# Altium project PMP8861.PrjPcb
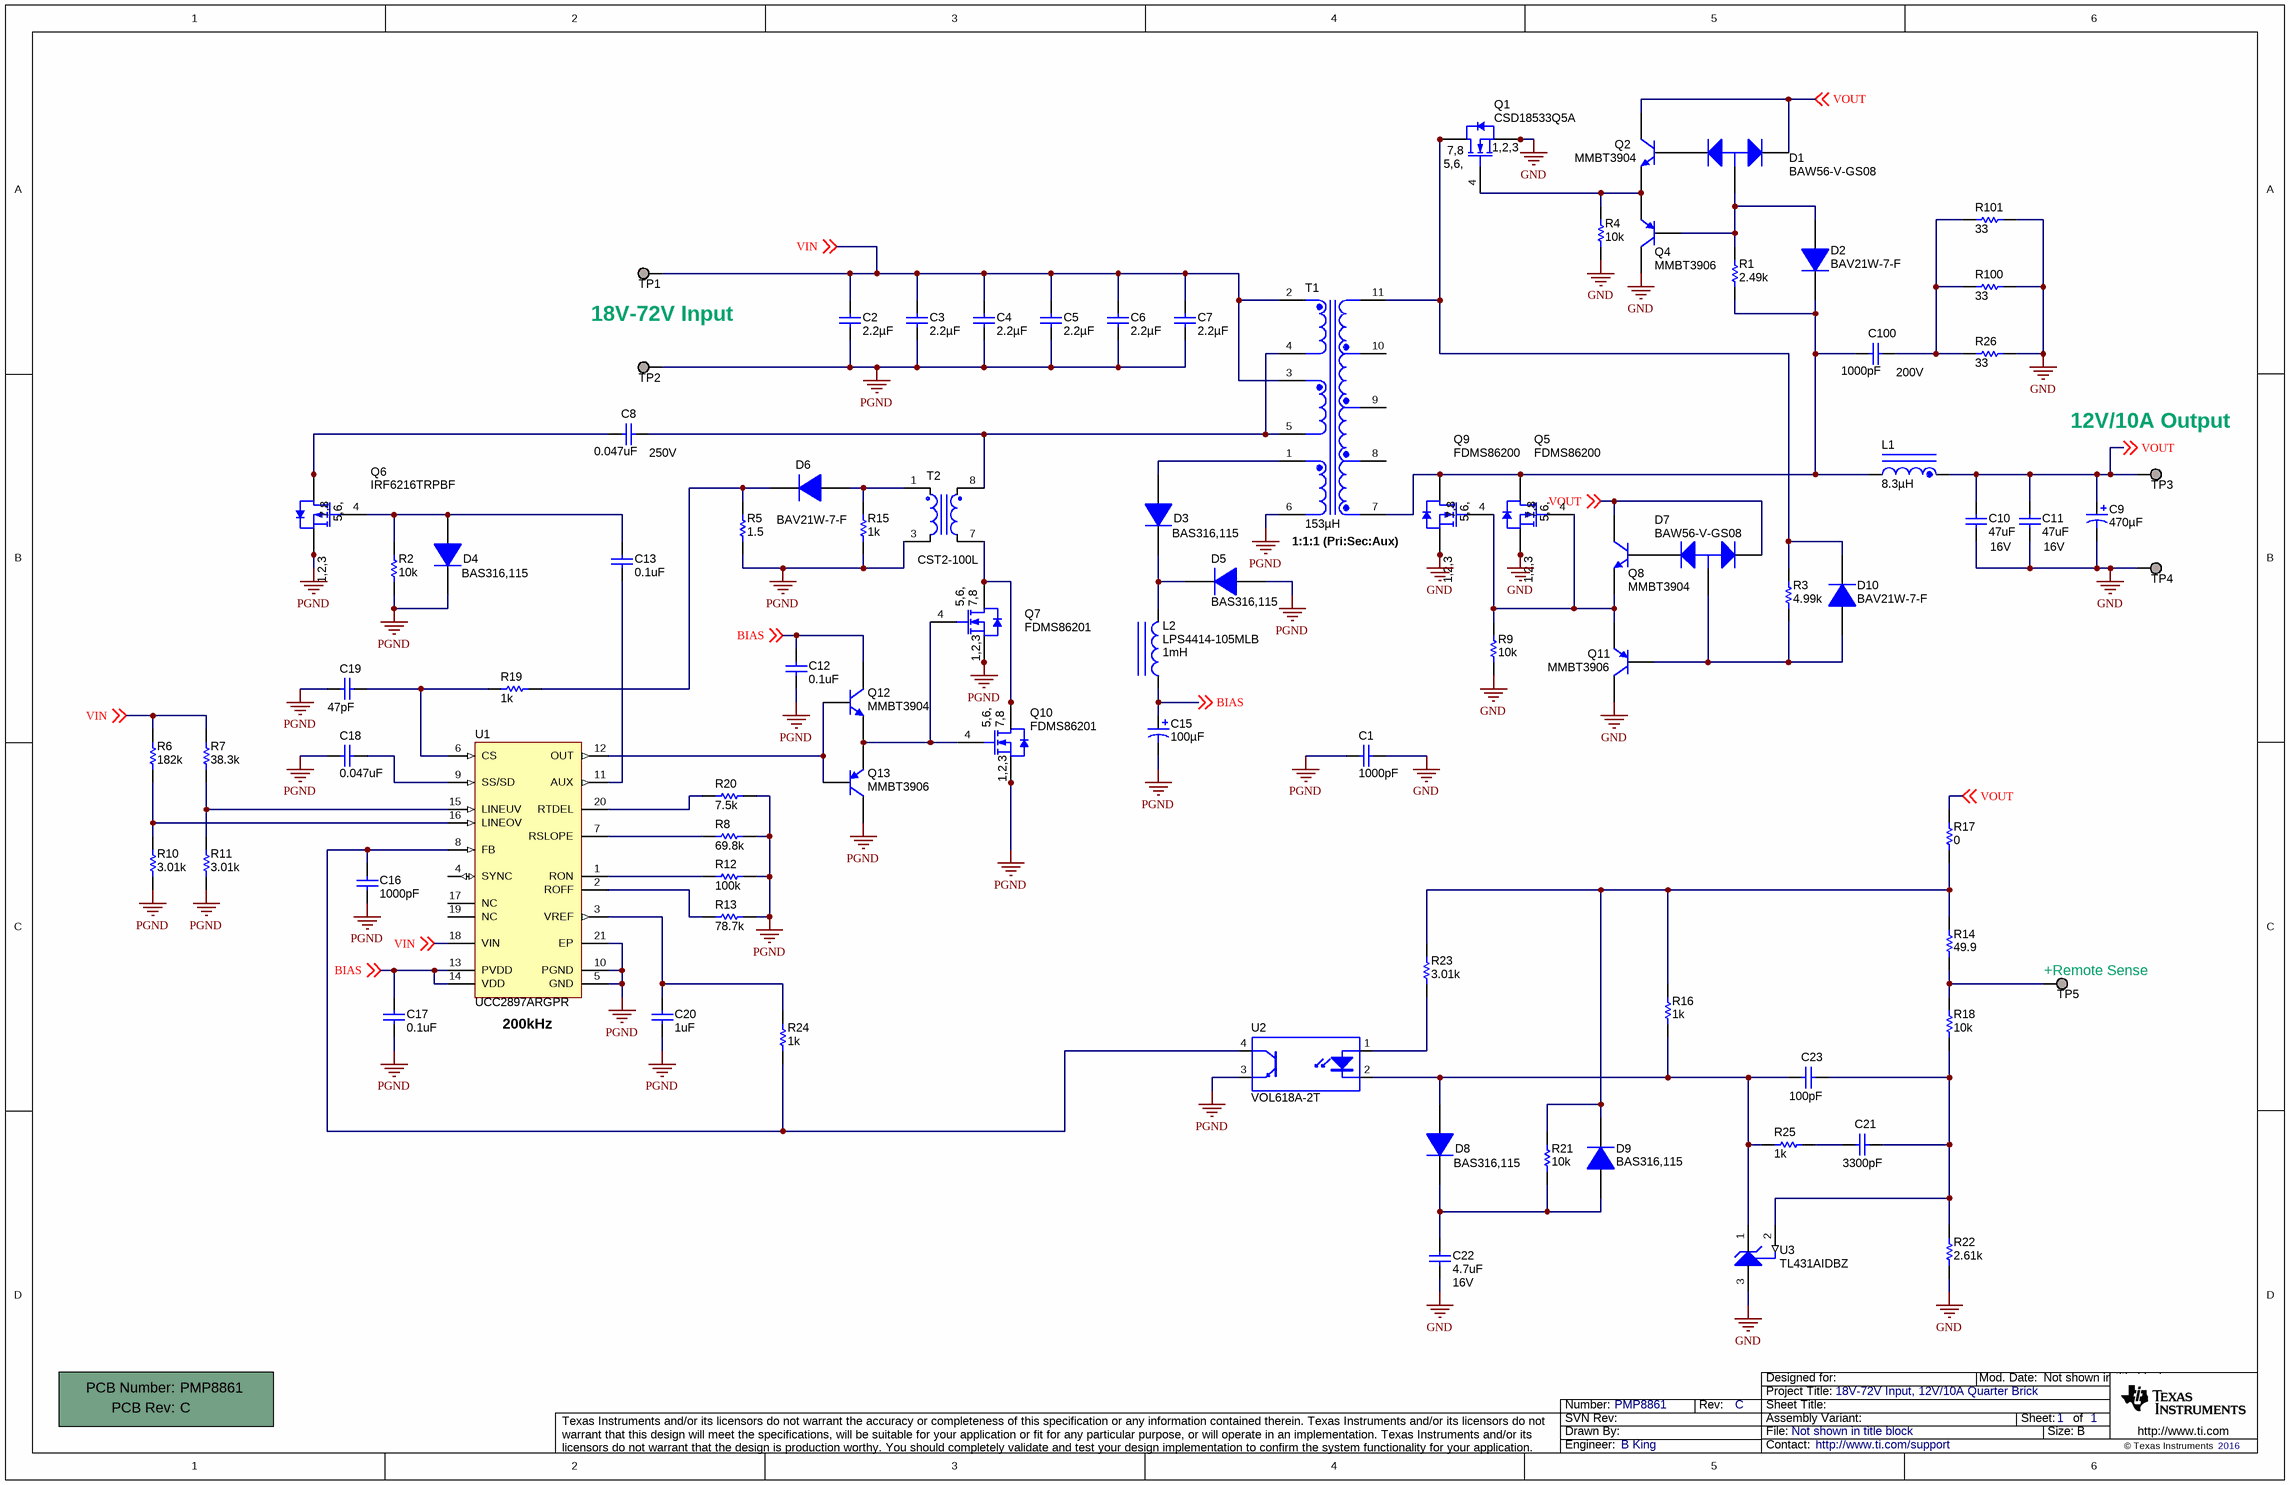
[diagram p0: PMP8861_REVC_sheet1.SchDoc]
TechSupport: http://www.ti.com/support; SCH_Rev: C; PRJ_Title: 18V-72V Input, 12V/10A Quarter Brick; PRJ_Number: PMP8861; PRJ_Engineer: B King; PCB_Rev: C; PCB_Layout: B King; CopyrightYear: 2016
1 sheet, 86 parts. Net scope: global (net labels, ports and power ports of the same name join across sheets).
Board file: PMP8861_REVC.PcbDoc

## Sheet PMP8861_REVC_sheet1.SchDoc
size 431 x 279 mm; Date: Not shown in title block; ApprovedBy: Not shown in title block; CheckedBy: Not shown in title block; Author: Not shown in title block; CompanyName: Not shown in title block; Engineer: Not shown in title block; Organization: Not shown in title block; Address1: Not shown in title block; Address2: Not shown in title block; Address3: Not shown in title block; Address4: Not shown in title block; DocumentNumber: 1; Revision: Use project parameter SCH_Rev; SheetNumber: 1; SheetTotal: 1; PageSetup: Record=PageOptions¦CenterHorizontal=True¦CenterVertical=True¦PrintScale=1.00¦XCorrection=1.00¦YCorrection=1.00¦PrintKind=0¦BorderSize=5000000¦LeftOffset=0¦BottomOffset=0¦Orientation=2¦PaperLength=1000¦PaperWidth=1000¦Scale=100¦PaperSource=15¦PrintQuality=600¦MediaType=1¦DitherType=10¦PaperKind=Letter¦PrintScaleMode=1

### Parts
!PCB1  Printed Circuit Board  (value not drawn)  (mechanical)
C1  ValueDisplayed: 1000pF  [1808_L]  (hidden comment: STD)
C2  ValueDisplayed: 2.2µF  [1210L]  (hidden comment: GRM32ER72A225KA35L)
C3  ValueDisplayed: 2.2µF  [1210L]  (hidden comment: GRM32ER72A225KA35L)
C4  ValueDisplayed: 2.2µF  [1210L]  (hidden comment: GRM32ER72A225KA35L)
C5  ValueDisplayed: 2.2µF  [1210L]  (hidden comment: GRM32ER72A225KA35L)
C6  ValueDisplayed: 2.2µF  [1210L]  (hidden comment: GRM32ER72A225KA35L)
C7  ValueDisplayed: 2.2µF  [1210L]  (hidden comment: GRM32ER72A225KA35L)
C8  value 0.047uF  Value2: 250V  [1206L]  (hidden comment: STD)
C9  ValueDisplayed: 470µF  [SM_RADIAL_F]  (hidden comment: EEE-FK1A471P)
C10  value 47uF  Value2: 16V  [1210L]  (hidden comment: STD)
C11  value 47uF  Value2: 16V  [1210L]  (hidden comment: STD)
C12  value 0.1uF  [0402L]  (hidden comment: STD)
C13  value 0.1uF  [0402L]  (hidden comment: STD)
C15  ValueDisplayed: 100µF  [SM_RADIAL_6.3BMM]  (hidden comment: EEHZA1E101XP)
C16  value 1000pF  [0402L]  (hidden comment: STD)
C17  value 0.1uF  [0402L]  (hidden comment: STD)
C18  value 0.047uF  [0402L]  (hidden comment: STD)
C19  value 47pF  [0402L]  (hidden comment: STD)
C20  value 1uF  [0402L]  (hidden comment: STD)
C21  value 3300pF  [0402L]  (hidden comment: STD)
C22  value 4.7uF  Value2: 16V  [1206L]  (hidden comment: STD)
C23  value 100pF  [0402L]  (hidden comment: STD)
C100  value 1000pF  Value2: 200V  [1206L]  (hidden comment: STD)
D1  BAW56-V-GS08  [SOT-23L]
D2  BAV21W-7-F  [SOD-123]
D3  BAS316,115  [sod-323]
D4  BAS316,115  [sod-323]
D5  BAS316,115  [sod-323]
D6  BAV21W-7-F  [SOD-123]
D7  BAW56-V-GS08  [SOT-23L]
D8  BAS316,115  [sod-323]
D9  BAS316,115  [sod-323]
D10  BAV21W-7-F  [SOD-123]
L1  ValueDisplayed: 8.3µH  [IND_PA2729]  (hidden comment: PA2729.802NL)
L2  LPS4414-105MLB  ValueDisplayed: 1mH  [LPS4414]
Q1  CSD18533Q5A  [TRANS_NexFET_Q5]
Q2  MMBT3904  [SOT-23L]
Q4  MMBT3906  [SOT-23L]
Q5  FDMS86200  [TRANS_Fairchild_PQFN08A]
Q6  IRF6216TRPBF  [SOIC-8]
Q7  FDMS86201  [TRANS_NexFET_Q5]
Q8  MMBT3904  [SOT-23L]
Q9  FDMS86200  [TRANS_Fairchild_PQFN08A]
Q10  FDMS86201  [TRANS_NexFET_Q5]
Q11  MMBT3906  [SOT-23L]
Q12  MMBT3904  [SOT-23L]
Q13  MMBT3906  [SOT-23L]
R1  value 2.49k  [0805L]  (hidden comment: STD)
R2  value 10k  [0402L]  (hidden comment: STD)
R3  value 4.99k  [0805L]  (hidden comment: STD)
R4  value 10k  [0402L]  (hidden comment: STD)
R5  value 1.5  [0805L]  (hidden comment: STD)
R6  value 182k  [0402L]  (hidden comment: STD)
R7  value 38.3k  [0402L]  (hidden comment: STD)
R8  value 69.8k  [0402L]  (hidden comment: STD)
R9  value 10k  [0402L]  (hidden comment: STD)
R10  value 3.01k  [0402L]  (hidden comment: STD)
R11  value 3.01k  [0402L]  (hidden comment: STD)
R12  value 100k  [0402L]  (hidden comment: STD)
R13  value 78.7k  [0402L]  (hidden comment: STD)
R14  value 49.9  [0402L]  (hidden comment: STD)
R15  value 1k  [0603L]  (hidden comment: STD)
R16  value 1k  [0402L]  (hidden comment: STD)
R17  value 0  [0402L]  (hidden comment: STD)
R18  value 10k  [0402L]  (hidden comment: STD)
R19  value 1k  [0402L]  (hidden comment: STD)
R20  value 7.5k  [0402L]  (hidden comment: STD)
R21  value 10k  [0402L]  (hidden comment: STD)
R22  value 2.61k  [0402L]  (hidden comment: STD)
R23  value 3.01k  [0603L]  (hidden comment: STD)
R24  value 1k  [0402L]  (hidden comment: STD)
R25  value 1k  [0402L]  (hidden comment: STD)
R26  ValueDisplayed: 33  [2512L]  (hidden comment: CRCW251233R0JNEG)
R100  ValueDisplayed: 33  [2512L]  (hidden comment: CRCW251233R0JNEG)
R101  ValueDisplayed: 33  [2512L]  (hidden comment: CRCW251233R0JNEG)
T1  ValueDisplayed: 153µH  [PA08XX]  (hidden comment: PA0801.004NL)
T2  CST2-100L  [XFMR_COILCRAFT_8X8p13MM6P]
TP1  Suggest using a net name here  [CONN_8600-0-05-80-00-00-03-0]  (value not drawn)
TP2  Suggest using a net name here  [CONN_8600-0-05-80-00-00-03-0]  (value not drawn)
TP3  Suggest using a net name here  [CONN_8952-0-05-80-00-00-03-0]  (value not drawn)
TP4  Suggest using a net name here  [CONN_8952-0-05-80-00-00-03-0]  (value not drawn)
TP5  Suggest using a net name here  [CONN_8600-0-05-80-00-00-03-0]  (value not drawn)
U1  UCC2897ARGPR  [RGP0020D]
U2  VOL618A-2T  [SOP254P1020X230-4]
U3  TL431AIDBZ  [DBZ0003A_L]

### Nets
GND: C1.1 C9.2(-) C10.2 C11.2 C22.2 Q1.1(S) Q1.2(S) Q1.3(S) Q4.3(C) Q5.1(S) Q5.2(S) Q5.3(S) Q9.1(S) Q9.2(S) Q9.3(S) Q11.3(C) R4.1 R9.1 R22.1 R26.2 R100.2 R101.2 TP4.1 U3.3(ANODE)
PGND: C1.2 C2.2 C3.2 C4.2 C5.2 C6.2 C7.2 C12.2 C15.2(-) C16.2 C17.2 C18.1 C19.2 C20.2 D4.1(K) D5.2(A) Q6.1(S) Q6.2(S) Q6.3(S) Q7.1(S) Q7.2(S) Q7.3(S) Q10.1(S) Q10.2(S) Q10.3(S) Q13.3(C) R2.1 R5.1 R8.1 R10.1 R11.1 R12.1 R13.1 R15.1 R20.1 T1.6 T2.3 TP2.1 U1.5(GND) U1.10(PGND) U1.21(EP) U2.3(E)
BIAS: C12.1 C15.1(+) C17.1 L2.1 Q12.3(C) U1.13(PVDD) U1.14(VDD) ; off-sheet BIAS
VIN: C2.1 C3.1 C4.1 C5.1 C6.1 C7.1 R6.2 R7.2 T1.2 T1.3 TP1.1 U1.18(VIN) ; off-sheet VIN
VOUT: C9.1(+) C10.1 C11.1 D1.1(K1) D7.1(K1) L1.1 Q2.3(C) Q8.3(C) R17.2 TP3.1 ; off-sheet VOUT
NetC8_1: C8.1 T1.4 T1.5 T2.8
NetC8_2: C8.2 Q6.5(D) Q6.6(D) Q6.7(D) Q6.8(D)
NetC13_1: C13.1 D4.2(A) Q6.4(G) R2.2
NetC13_2: C13.2 U1.11(AUX)
NetC16_1: C16.1 R24.1 U1.8(FB) U2.4(C)
NetC18_2: C18.2 U1.9(SS/SD)
NetC19_1: C19.1 R19.2 U1.6(CS)
NetC20_1: C20.1 R24.2 U1.3(VREF)
NetC21_1: C21.1 C23.1 R18.1 R22.2 U3.2(REF)
NetC21_2: C21.2 R25.1
NetC22_1: C22.1 D8.1(K) D9.2(A) R21.1
NetC23_2: C23.2 D8.2(A) R16.1 R25.2 U2.2(K) U3.1(CATHODE)
NetC100_1: C100.1 R26.1 R100.1 R101.1
NetC100_2: C100.2 D2.1(K) L1.2 Q5.5(D) Q5.6(D) Q5.7(D) Q5.8(D) Q9.5(D) Q9.6(D) Q9.7(D) Q9.8(D) R1.1 T1.7
NetD1_2: D1.2(K2) Q2.1(B)
NetD1_3: D1.3(A) D2.2(A) Q4.1(B) R1.2
NetD3_1: D3.1(K) D5.1(K) L2.2
NetD3_2: D3.2(A) T1.1
NetD6_1: D6.1(K) R5.2 R19.1
NetD6_2: D6.2(A) R15.2 T2.1
NetD7_2: D7.2(K2) Q8.1(B)
NetD7_3: D7.3(A) D10.2(A) Q11.1(B) R3.1
NetD9_1: D9.1(K) R14.2 R16.2 R17.1 R21.2 R23.2
NetD10_1: D10.1(K) Q1.5(D) Q1.6(D) Q1.7(D) Q1.8(D) Q1.9(D) R3.2 T1.11
NetQ1_4: Q1.4(G) Q2.2(E) Q4.2(E) R4.2
NetQ5_4: Q5.4(G) Q8.2(E) Q9.4(G) Q11.2(E) R9.2
NetQ7_4: Q7.4(G) Q10.4(G) Q12.2(E) Q13.2(E)
NetQ7_5: Q7.5(D) Q7.6(D) Q7.7(D) Q7.8(D) Q7.9(D) Q10.5(D) Q10.6(D) Q10.7(D) Q10.8(D) Q10.9(D) T2.7
NetQ12_1: Q12.1(B) Q13.1(B) U1.12(OUT)
NetR6_1: R6.1 R10.2 U1.16(LINEOV)
NetR7_1: R7.1 R11.2 U1.15(LINEUV)
NetR8_2: R8.2 U1.7(RSLOPE)
NetR12_2: R12.2 U1.1(RON)
NetR13_2: R13.2 U1.2(ROFF)
NetR14_1: R14.1 R18.2 TP5.1
NetR20_2: R20.2 U1.20(RTDEL)
NetR23_1: R23.1 U2.1(A)

Not connected (* = marked no-connect by the designer): T1 8 9 10; U1 4(SYNC) 17(NC) 19(NC)

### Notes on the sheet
- 18V-72V Input
- (near TP3) 12V/10A Output
- (near T1) 1:1:1 (Pri:Sec:Aux)
- (near TP5) +Remote Sense
- (near U1) 200kHz

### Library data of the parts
!PCB1 = PCB: Manufacturer: Any; PartNumber: PMP8861; SymbolCreator: a0412235
C1 = VJ1808Y102KXEAT5Z: CAP, CERM, 1000pF, 3kV, 1808; Polarized: N; CompType: Capacitor; U/M: EA; Cap_F: 0.000000001; Tolerance_%: 10; Value1: Unknown; TempCo: X7R; TaMin_C: -55; TaMax_C: 125; Cap_Case: 1808
C2-C7 = GRM32ER72A225KA35L: CAP, CERM, 2.2uF, 100V, +/-10%, X7R, 1210; Manufacturer: MuRata; Polarized: N; CompType: Capacitor; U/M: EA; Cap_F: 0.0000022; Tolerance_%: 10; ESR_Ohm: 0.007; Value1: 0.007 ohm; VDC_V: 100; IRMS_A: 4.4; TaMin_C: -55; TaMax_C: 125; Cap_Case: 1210
C8 = C1206C103K5RACTU: CAP, CERM, 250V, +/-10%, X7R, 1206; Polarized: N; CompType: Capacitor; ValueDisplayed: 0.01µF; U/M: EA; Cap_F: 0.00000001; Tolerance_%: 10; ESR_Ohm: 0.155; Value1: 0.155 ohm; VDC_V: 50; IRMS_A: 0.416; TaMin_C: -55; TaMax_C: 125; Cap_Case: 1206
C9 = EEE-FK1A471P: CAP, AL, 470uF, 10V, +/-20%, 0.16 ohm, SMD; Manufacturer: Panasonic; Polarized: Y; CompType: Capacitor; U/M: EA; Cap_F: 0.00047; Tolerance_%: 20; VDC_V: 10; ESR_Ohm: 0.16; IRMS_A: 0.6; TaMin_C: -55; TaMax_C: 105; Cap_Case: F
C10 C11 = VJ1210Y473KXGAT5Z: CAP, CERM, 16V, +/-10%, X7R, 1210; Polarized: N; CompType: Capacitor; ValueDisplayed: 0.047µF; U/M: EA; Cap_F: 0.000000047; Tolerance_%: 10; Value1: Unknown; VDC_V: 1000; TaMin_C: -55; TaMax_C: 125; Cap_Case: 1210
C12 C13 C16-C18 = 04025C132KAT2A: CAP, CERM, 25V, +/-10%, X7R, 0402; Polarized: N; CompType: Capacitor; ValueDisplayed: 1300pF; U/M: EA; Cap_F: 0.0000000013; Tolerance_%: 10; Value1: Unknown; VDC_V: 50; Value2: 50V; TaMin_C: -55; TaMax_C: 125; Cap_Case: 0402
C15 = EEHZA1E101XP: CAP, AL, 100uF, 25V, +/-20%, 30 ohm, SMD; Manufacturer: Panasonic; Polarized: Y; CompType: Capacitor; U/M: EA; Cap_F: 0.0001; Tolerance_%: 20; Value1: 30 ohm; VDC_V: 25; ESR_Ohm: 30; IRMS_A: 2; TaMin_C: -55; TaMax_C: 105
C19 C21 C23 = 04025C132KAT2A: CAP, CERM, 50V, +/-10%, X7R, 0402; Polarized: N; CompType: Capacitor; ValueDisplayed: 1300pF; U/M: EA; Cap_F: 0.0000000013; Tolerance_%: 10; Value1: Unknown; VDC_V: 50; TaMin_C: -55; TaMax_C: 125; Cap_Case: 0402
C20 = 04025C132KAT2A: CAP, CERM, 16V, +/-10%, X5R, 0402; Polarized: N; CompType: Capacitor; ValueDisplayed: 1300pF; U/M: EA; Cap_F: 0.0000000013; Tolerance_%: 10; Value1: Unknown; VDC_V: 50; Value2: 50V; TempCo: X7R; TaMin_C: -55; TaMax_C: 125; Cap_Case: 0402
C22 = C1206C103K5RACTU: CAP, CERM, 16V, +/-10%, X7R, 1206; Polarized: N; CompType: Capacitor; ValueDisplayed: 0.01µF; U/M: EA; Cap_F: 0.00000001; Tolerance_%: 10; ESR_Ohm: 0.155; Value1: 0.155 ohm; VDC_V: 50; IRMS_A: 0.416; TaMin_C: -55; TaMax_C: 125; Cap_Case: 1206
C100 = C1206C103K5RACTU: CAP, CERM, 200V, +/-10%, NP0, 1206; Polarized: N; CompType: Capacitor; ValueDisplayed: 0.01µF; U/M: EA; Cap_F: 0.00000001; Tolerance_%: 10; ESR_Ohm: 0.155; Value1: 0.155 ohm; VDC_V: 50; TempCo: X7R; IRMS_A: 0.416; TaMin_C: -55; TaMax_C: 125; Cap_Case: 1206
D1 D7 = BAW56-V-GS08: Diode, Switching, 70V, 0.25A, SOT-23; Manufacturer: Vishay-Semiconductor; SymbolCreator: a0412235; U/M: EA; Vf_V: 0; Value: 0V; Io_A: 0.25; Vr_V: 70; TJmax_C: 150
D2 D6 D10 = BAV21W-7-F: Diode, Switching, 200V, 0.2A, SOD-123; Manufacturer: Diodes Inc.; Value: 1.25V; U/M: EA; Vf_V: 1.25; Io_A: 0.2; Vr_V: 200; TJmax_C: 150
D3-D5 D8 D9 = BAS316,115: Diode, Ultrafast, 100V, 0.25A, SOD-323; Manufacturer: NXP Semiconductor; Value: 1.4V; U/M: EA; Vf_V: 1.4; Io_A: 0.25; Vr_V: 100; TJmax_C: 150
L1 = PA2729.802NL: Inductor, Shielded Drum Core, Ferrite, 8.3 µH, 13.3 A, 0.0051 ohm, SMD; Manufacturer: Pulse Engineering; Value: 8.3uH; SymbolCreator: a0412235; Ind_H: 8.30E-06; Imax_A: 13.3; Irms: 13.3A @ 40C rise; Isat: 16.8A @ 20% inductance drop; DCR_ohm: 0.0051; Value2: 13.3A; AEC Category: Q200
L2 = LPS4414-105MLB: Inductor, Shielded Drum Core, Ferrite, 1mH, 0.11A, 16.3 ohm, SMD; Manufacturer: Coilcraft; Ind_H: 1.0E-3; Imax_A: 0.11; Irms: 0.13A @ 40C rise; Isat: 0.106A @ 30% inductance drop; DCR_ohm: 16.3; U/M: EA
Q1 = CSD16321Q5: MOSFET N-CH 60V 17A 8SON; Manufacturer: Texas Instruments; Alternate Manufacturer: None; Value: 25V; U/M: EA; ChType: N; VdsMax_V: 25; Value1: 0.0021 ohm; Rdson45_Ohm: 0.0021; Value2: 14 nC; QgTyp_nC: 14; Vgs_V: 10; IdsMax_A: 100
Q2 Q8 Q12 = MMBT3904, Fairchild Semiconductor: Transistor, NPN, 40V, 0.2A, SOT-23; CompType: BJT; PNP: 0; NPN: 1; Vceo_V: 40; Vcesat1_V: 0.2; Value: 0.2V; HfeMax: 300; TaMin_C: -55; TaMax_C: 150; U/M: EA
Q4 Q11 Q13 = MMBT3906, Fairchild Semiconductor: Transistor, PNP, 40V, 0.2A, SOT-23; CompType: BJT; PNP: 1; NPN: 0; Vceo_V: 40; Vcesat1_V: 0.25; Value: 0.25V; IcRated_A: 0.2; HfeMax: 300; TaMin_C: -55; TaMax_C: 150; U/M: EA
Q5 Q9 = FDMS86200: MOSFET, N-CH, 150V, 35A, PQFN08A; Manufacturer: Fairchild Semiconductor; Alternate Manufacturer: None; U/M: EA; ChType: N; VdsMax_V: 150; Value1: 101 ohm; Rdson45_Ohm: 101; Value2: 33 nC; QgTyp_nC: 33; Vgs_V: 20; IdsMax_A: 35
Q6 = SI4427BDY-E3: MOSFET P-CH 150V 2.2A 8-SOIC; Manufacturer: International Rectifier; Alternate Manufacturer: None; Value: -30V; U/M: EA; ChType: P; VdsMax_V: -30; Value1: 0.0105 ohm; Rdson45_Ohm: 0.0105; Value2: 47.2 nC; QgTyp_nC: 47.2; Vgs_V: -12; IdsMax_A: -9.7
Q7 Q10 = CSD16321Q5: MOSFET N-CH 120V POWER56; Manufacturer: Fairchild; Alternate Manufacturer: None; Value: 25V; U/M: EA; ChType: N; VdsMax_V: 25; Value1: 0.0021 ohm; Rdson45_Ohm: 0.0021; Value2: 14 nC; QgTyp_nC: 14; Vgs_V: 10; IdsMax_A: 100
R1 R3 R5 = CRCW08050000Z0EA: RES, 1%, 0.125W, 0805; CompType: Resistor; Res_ohm: 0; Value_Code: 0000; Tolerance_%: 5; Value1: 5%; Power_W: 0.125; VDC_V: 150; TempCo: 200 ppm/C; EIA_Code: E24; U/M: EA
R2 R4 R6-R14 R16-R22 R24 R25 = CRCW0402133RFKED: RES, 1%, 0.063W, 0402; CompType: Resistor; Res_ohm: 133; Value_Code: 133R; Tolerance_%: 1; Power_W: 0.063; VDC_V: 50; TempCo: 100 ppm/C; EIA_Code: E96; U/M: EA
R15 R23 = CRCW06030000Z0EA: RES,  1%, 0.1W, 0603; CompType: Resistor; Res_ohm: 0; Value_Code: 0000; Tolerance_%: 5; Value1: 5%; Power_W: 0.1; VDC_V: 75; TempCo: 200 ppm/C; EIA_Code: E24; U/M: EA
R26 R100 R101 = CRCW251233R0JNEG: RES, 33, 5%, 1 W, AEC-Q200 Grade 0, 2512; Manufacturer: Vishay-Dale; CompType: Resistor; Value_Code: 33R0; Tolerance_%: 5; Power_W: 1; Value2: 1W; VDC_V: 500; TempCo: 200 ppm/C; EIA_Code: E24; U/M: EA; Value: 33; AEC Category: Q200; AEC Qualified: Y; AEC Grade: 0
T1 = PA0801.004NL: Transformer, 153 uH, SMT; Manufacturer: Pulse Engineering; SymbolCreator: Altium; Value: 153uH; Lp: 153; DCR_ohm: 0.0175; LeakageL: 0.45; Ns1toNp: 0.25; Rs1: 0.007
T2 = CST2-100L: Transformer, 2000uH, SMT; Manufacturer: Coilcraft; SymbolCreator: a0799628; U/M: EA
TP1 TP2 TP5 = 8600-0-05-80-00-00-03-0: PCB Pin, solderless Pressfit, Tin over Nickel; Manufacturer: Mill-Max; CompType: PCB Pin; U/M: EA
TP3 TP4 = 8952-0-05-80-00-00-03-0: PCB Pin, solderless Pressfit, Tin over Nickel; Manufacturer: Mill-Max; CompType: PCB Pin; U/M: EA
U1 = UCC2897ARGPR: Advanced Active Clamp PWM Controller with Current Control, -40 to +125 degC, 20-pin QFN (RGP), Green (RoHS & no Sb/Br); Manufacturer: Texas Instruments; Alternate Manufacturer: None; Alternate PartNumber: Equivalent; Frequency(Max)(kHz): 1000; Rating: Catalog; Regulated Outputs(#): 1
U2 = VOL618A-2T: OPTOCOUPLR PHOTOTRANS 125% 4LSOP; Manufacturer: Vishay-Semiconductor; CompType: OPTOCOUPLER; U/M: EA
U3 = TL431AIDBZ: PRECISION PROGRAMMABLE REFERENCE, DBZ0003A; Alternate Manufacturer: None; Manufacturer: Texas Instruments; SymbolCreator: a0412235; CompType: IC; U/M: EA

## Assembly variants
001: all parts fitted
